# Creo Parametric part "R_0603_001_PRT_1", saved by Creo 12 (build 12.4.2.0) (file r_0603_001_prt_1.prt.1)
Units: Custom; MM, KILOGRAM, SECS

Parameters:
  PTC_WM_ITERATION = "0"
  PTC_WM_VERSION = "-.0"
  PTC_WM_LIFECYCLE_STATE = "In Work"
  PTC_WM_LIFECYCLE = "MO_CADDocument"
  PTC_WM_CREATED_BY = "Maximilian Roepper (Z0017RMS: MO)"
  PTC_WM_CREATED_ON = "18-Sep-26 11:36:42 AM"
  PTC_WM_MODIFIED_BY = "Maximilian Roepper (Z0017RMS: MO)"
  PTC_WM_MODIFIED_ON = "18-Sep-26 11:36:46 AM"
  PDMLINKNUMBER = "PDM000071455310"
  PTC_WM_NAME = "r_0603_001_prt_1.prt"
  PTC_WM_NUMBER = "PDM000071455310"

Other parameters: WEIGHT, WEIGHT_FACTOR, WEIGHT_ADD, _MASS_TEMP, _DIFF_TEMP, MC_ERRORS, SUPPLIER

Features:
  1. coordinate system
  2. datum plane "PRT_YZ"
  3. datum plane "PRT_XY"
  4. datum plane "PRT_XZ"
  5. coordinate system
  6. datum axis
  7. datum axis
  8. datum axis
  9. coordinate system
  10. imported feature
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
Other named items: PRT, SIEMENS_MO, DRW_VIEW_ORG, PRT_X, PRT_Y, PRT_Z, CS0, ROUGH_GROB

Layers: 00_STD_CSYS-KSYS, 01_STD_PLANES-EBENEN, 02_STD_AXES-ACHSEN, 03_STD_CSYS-KSYS, 24_IMPORT_FEAT-IMPORT_KE

Surfaces: 18 plane, 8 cylinder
